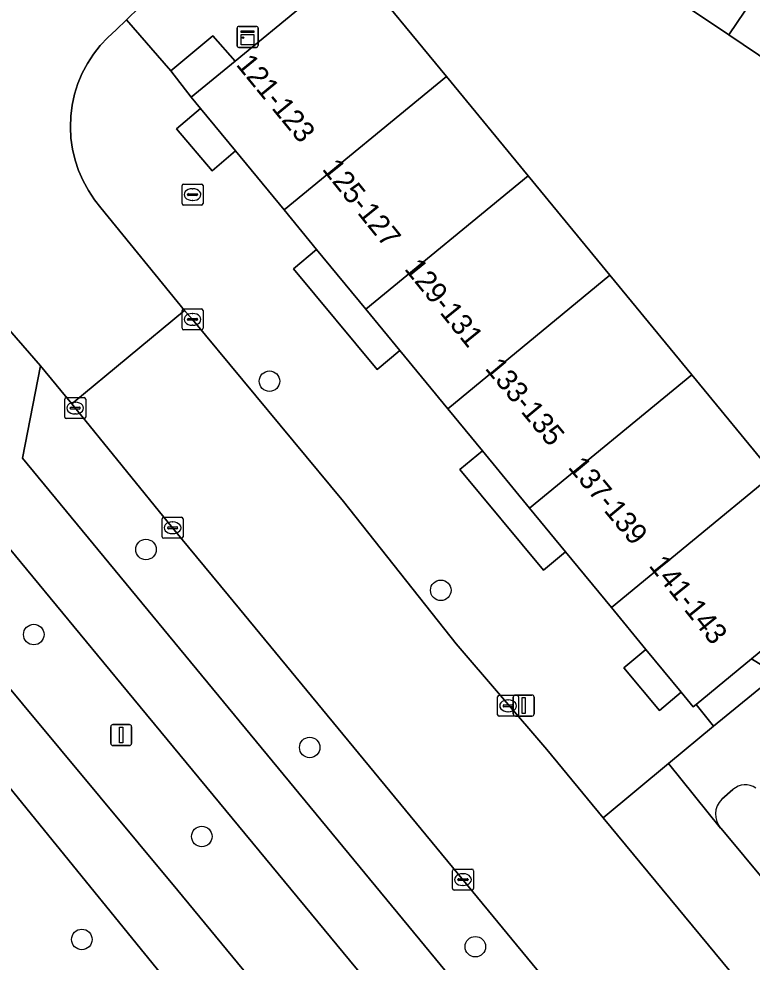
# Model space of a CAD drawing. Extents: x 159279 to 160377, y 384531 to 385888.
# Drawn here: x 159611.52 to 159646.49, y 384936.18 to 384981.15 of the extents above; entities that cross this region are included whole.
import ezdxf

# ---------------------------------------------------------------- set-up
doc = ezdxf.new("R2010")
doc.units = 0
for name, color, linetype in [('IMGEO_Berm_groen', 7, 'Continuous'), ('IMGEO_Boom', 7, 'Continuous'), ('IMGEO_Brandkraan', 7, 'Continuous'), ('IMGEO_Erf', 7, 'Continuous'), ('IMGEO_Fietspad_open', 7, 'Continuous'), ('IMGEO_Groenvoorziening', 7, 'Continuous'), ('IMGEO_Kast', 7, 'Continuous'), ('IMGEO_Kolk', 7, 'Continuous'), ('IMGEO_Lichtmast', 7, 'Continuous'), ('IMGEO_Pand', 7, 'Continuous'), ('IMGEO_Pand_nummerreeks', 7, 'Continuous'), ('IMGEO_Rijbaan_lokaal_open', 7, 'Continuous'), ('IMGEO_Voetpad_halfverhard', 7, 'Continuous'), ('IMGEO_Voetpad_open', 7, 'Continuous')]:
    doc.layers.add(name, color=color, linetype=linetype)

msp = doc.modelspace()

# ---------------------------------------------------------------- linework, layer by layer
at = {"layer": 'IMGEO_Berm_groen'}
for points in [[(159644.994, 384925.184), (159640.15, 384931.055), (159637.855, 384933.836), (159632.942, 384939.791), (159621.521, 384953.652), (159618.858, 384956.883), (159614.051, 384962.787), (159612.55, 384964.603), (159611.693, 384960.205), (159637.6, 384928.803), (159664.904, 384895.82), (159666.72, 384893.575), (159667.536, 384892.609), (159672.097, 384887.337), (159677.11, 384882.494), (159678.409, 384881.386), (159681.234, 384884.662), (159679.004, 384886.957), (159668.558, 384897.795)], [(159633.273, 384929.038), (159616.704, 384949.08), (159611.069, 384955.91), (159609.789, 384950.769), (159619.101, 384939.596), (159642.409, 384911.351), (159643.599, 384910.093), (159663.539, 384885.894)]]:
    msp.add_lwpolyline(points, dxfattribs=at)
at = {"layer": 'IMGEO_Boom'}
for centre in [(159623.475, 384963.871), (159617.585, 384955.848), (159631.643, 384953.903), (159612.235, 384951.792), (159625.394, 384946.411), (159620.248, 384942.166), (159614.527, 384937.258), (159633.291, 384936.911)]:
    msp.add_circle(centre, 0.489, dxfattribs=at)
at = {"layer": 'IMGEO_Brandkraan'}
for p, q in [((159619.305, 384972.343), (159619.305, 384973.195)), ((159619.38, 384973.269), (159620.232, 384973.269)), ((159619.793, 384973.049), (159619.818, 384973.049)), ((159620.306, 384973.195), (159620.306, 384972.343)), ((159619.564, 384972.763), (159619.564, 384972.775)), ((159620.002, 384972.726), (159619.604, 384972.726)), ((159619.607, 384972.812), (159620.005, 384972.812)), ((159619.816, 384972.489), (159619.791, 384972.489)), ((159620.048, 384972.775), (159620.048, 384972.763)), ((159620.232, 384972.269), (159619.38, 384972.269))]:
    msp.add_line(p, q, dxfattribs=at)
for points in [[(159619.305, 384972.343), (159619.305, 384973.195)], [(159619.38, 384973.269), (159620.232, 384973.269)], [(159620.306, 384973.195), (159620.306, 384972.343)], [(159620.232, 384972.269), (159619.38, 384972.269)]]:
    msp.add_lwpolyline(points, dxfattribs=at)
for centre, radius, start, end in [((159619.382, 384973.193), 0.0765, 91.552, 178.448), ((159619.382, 384973.193), 0.0765, 91.552, 178.448), ((159620.23, 384973.193), 0.0765, 1.552, 88.448), ((159620.23, 384973.193), 0.0765, 1.552, 88.448), ((159619.604, 384972.772), 0.0403, 85.8775, 175.7526), ((159619.601, 384972.762), 0.0366, 178.938, 274.7102), ((159620.005, 384972.769), 0.043, 264.8664, 352.4533), ((159620.009, 384972.774), 0.0386, 1.7309, 96.639), ((159619.382, 384972.345), 0.0765, 181.552, 268.448), ((159619.382, 384972.345), 0.0765, 181.552, 268.448), ((159620.23, 384972.345), 0.0765, 271.552, 358.448), ((159620.23, 384972.345), 0.0765, 271.552, 358.448)]:
    msp.add_arc(centre, radius, start, end, dxfattribs=at)
for centre, major_axis, ratio, start_param, end_param in [((159619.792, 384972.769), (-0.387, 0.002), 0.722429, 4.712389, 7.853982), ((159619.817, 384972.769), (-0.39, 0.002), 0.717154, 1.570796, 4.712389)]:
    msp.add_ellipse(centre, major_axis=major_axis, ratio=ratio, start_param=start_param, end_param=end_param, dxfattribs=at)
at = {"layer": 'IMGEO_Erf'}
msp.add_lwpolyline([(159660.128, 384970.454), (159658.021, 384971.872), (159655.913, 384973.29), (159653.806, 384974.708), (159651.699, 384976.126), (159649.591, 384977.544), (159647.484, 384978.963), (159645.377, 384980.381), (159643.269, 384981.799), (159641.162, 384983.217), (159639.055, 384984.635), (159640.555, 384986.863), (159642.662, 384985.445), (159644.769, 384984.027), (159646.877, 384982.609), (159648.984, 384981.191), (159651.091, 384979.773), (159653.199, 384978.355), (159655.306, 384976.937), (159657.413, 384975.519), (159659.521, 384974.101), (159661.628, 384972.683), (159663.761, 384971.248), (159662.262, 384969.019)], close=True, dxfattribs=at)
msp.add_lwpolyline([(159625.123, 384981.838), (159627.485, 384983.785), (159631.916, 384978.405), (159635.813, 384973.663), (159639.71, 384968.922), (159643.607, 384964.181), (159647.503, 384959.44)], dxfattribs=at)
at = {"layer": 'IMGEO_Fietspad_open'}
msp.add_lwpolyline([(159637.6, 384928.803), (159611.693, 384960.205), (159612.55, 384964.603), (159610.018, 384967.509), (159609.905, 384967.64), (159609.049, 384963.374), (159597.738, 384977.083), (159595.245, 384975.018), (159595.683, 384974.49), (159603.858, 384964.651), (159608.885, 384958.557), (159609.221, 384958.15), (159611.069, 384955.91), (159616.704, 384949.08), (159633.273, 384929.038), (159641.684, 384918.846), (159646.291, 384913.294), (159653.523, 384904.47)], dxfattribs=at)
at = {"layer": 'IMGEO_Groenvoorziening'}
for points in [[(159663.23, 384881.856), (159641.152, 384908.338), (159619.729, 384933.865), (159611.086, 384944.483)], [(159645.567, 384944.403), (159645.039, 384943.946)], [(159645.006, 384942.551), (159650.423, 384936.055), (159653.648, 384934.296), (159660.389, 384926.303), (159662.126, 384927.047)]]:
    msp.add_lwpolyline(points, dxfattribs=at)
for centre, radius, start, end in [((159646.165, 384943.725), 0.904, 55.8605, 131.389), ((159645.749, 384943.231), 1.008, 134.8302, 222.4595)]:
    msp.add_arc(centre, radius, start, end, dxfattribs=at)
at = {"layer": 'IMGEO_Kast'}
for p, q in [((159621.931, 384979.862), (159621.931, 384980.703)), ((159621.931, 384980.703), (159621.931, 384979.862)), ((159622.006, 384980.787), (159622.847, 384980.787)), ((159622.847, 384980.787), (159622.006, 384980.787)), ((159622.931, 384980.712), (159622.931, 384979.871)), ((159622.931, 384979.871), (159622.931, 384980.712)), ((159622.856, 384979.787), (159622.015, 384979.787)), ((159622.015, 384979.787), (159622.856, 384979.787))]:
    msp.add_line(p, q, dxfattribs=at)
for points in [[(159622.126, 384980.577), (159622.726, 384980.577), (159622.726, 384980.492), (159622.126, 384980.492), (159622.126, 384980.577)], [(159622.126, 384980.402), (159622.726, 384980.402), (159622.726, 384979.913), (159622.126, 384979.913), (159622.126, 384980.402)]]:
    msp.add_lwpolyline(points, dxfattribs=at)
msp.add_circle((159622.21, 384980.251), 0.0377, dxfattribs=at)
for centre, start, end in [((159622.009, 384980.709), 92.4484, 184.2845), ((159622.009, 384980.709), 92.4484, 184.2845), ((159622.853, 384980.709), 2.4484, 94.2845), ((159622.853, 384980.709), 2.4484, 94.2845), ((159622.009, 384979.865), 182.4484, 274.2845), ((159622.009, 384979.865), 182.4484, 274.2845), ((159622.853, 384979.865), 272.4484, 4.2845), ((159622.853, 384979.865), 272.4484, 4.2845)]:
    msp.add_arc(centre, 0.0779, start, end, dxfattribs=at)
at = {"layer": 'IMGEO_Kolk'}
for p, q in [((159619.304, 384966.393), (159619.304, 384967.245)), ((159619.379, 384967.319), (159620.231, 384967.319)), ((159619.792, 384967.099), (159619.817, 384967.099)), ((159620.305, 384967.245), (159620.305, 384966.393)), ((159619.563, 384966.813), (159619.563, 384966.825)), ((159620.001, 384966.776), (159619.603, 384966.776)), ((159619.606, 384966.862), (159620.004, 384966.862)), ((159620.047, 384966.825), (159620.047, 384966.813)), ((159620.231, 384966.319), (159619.379, 384966.319)), ((159619.815, 384966.539), (159619.79, 384966.539)), ((159613.709, 384962.163), (159613.709, 384963.015)), ((159613.784, 384963.089), (159614.636, 384963.089)), ((159614.71, 384963.015), (159614.71, 384962.163)), ((159613.968, 384962.583), (159613.968, 384962.595)), ((159614.406, 384962.546), (159614.008, 384962.546)), ((159614.011, 384962.632), (159614.409, 384962.632)), ((159614.197, 384962.869), (159614.222, 384962.869)), ((159614.452, 384962.595), (159614.452, 384962.583)), ((159614.636, 384962.089), (159613.784, 384962.089)), ((159614.22, 384962.309), (159614.195, 384962.309)), ((159618.356, 384956.457), (159618.356, 384957.309)), ((159618.431, 384957.383), (159619.283, 384957.383)), ((159618.844, 384957.163), (159618.869, 384957.163)), ((159619.357, 384957.309), (159619.357, 384956.457)), ((159618.615, 384956.877), (159618.615, 384956.889)), ((159619.053, 384956.84), (159618.655, 384956.84)), ((159618.658, 384956.926), (159619.056, 384956.926)), ((159619.099, 384956.889), (159619.099, 384956.877)), ((159619.283, 384956.383), (159618.431, 384956.383)), ((159618.867, 384956.603), (159618.842, 384956.603)), ((159634.353, 384947.97), (159634.353, 384948.822)), ((159634.428, 384948.896), (159635.28, 384948.896)), ((159634.841, 384948.676), (159634.866, 384948.676)), ((159635.354, 384948.822), (159635.354, 384947.97)), ((159634.612, 384948.39), (159634.612, 384948.402)), ((159635.05, 384948.353), (159634.652, 384948.353)), ((159634.655, 384948.439), (159635.053, 384948.439)), ((159635.096, 384948.402), (159635.096, 384948.39)), ((159635.28, 384947.896), (159634.428, 384947.896)), ((159634.864, 384948.116), (159634.839, 384948.116)), ((159632.201, 384939.684), (159632.201, 384940.536)), ((159632.276, 384940.61), (159633.128, 384940.61)), ((159633.202, 384940.536), (159633.202, 384939.684)), ((159632.46, 384940.104), (159632.46, 384940.116)), ((159632.898, 384940.067), (159632.5, 384940.067)), ((159632.503, 384940.153), (159632.901, 384940.153)), ((159632.689, 384940.39), (159632.714, 384940.39)), ((159632.944, 384940.116), (159632.944, 384940.104)), ((159633.128, 384939.61), (159632.276, 384939.61)), ((159632.712, 384939.83), (159632.687, 384939.83))]:
    msp.add_line(p, q, dxfattribs=at)
for points in [[(159619.304, 384966.393), (159619.304, 384967.245)], [(159619.379, 384967.319), (159620.231, 384967.319)], [(159620.305, 384967.245), (159620.305, 384966.393)], [(159620.231, 384966.319), (159619.379, 384966.319)], [(159613.709, 384962.163), (159613.709, 384963.015)], [(159613.784, 384963.089), (159614.636, 384963.089)], [(159614.71, 384963.015), (159614.71, 384962.163)], [(159614.636, 384962.089), (159613.784, 384962.089)], [(159618.356, 384956.457), (159618.356, 384957.309)], [(159618.431, 384957.383), (159619.283, 384957.383)], [(159619.357, 384957.309), (159619.357, 384956.457)], [(159619.283, 384956.383), (159618.431, 384956.383)], [(159634.353, 384947.97), (159634.353, 384948.822)], [(159634.428, 384948.896), (159635.28, 384948.896)], [(159635.354, 384948.822), (159635.354, 384947.97)], [(159635.28, 384947.896), (159634.428, 384947.896)], [(159632.201, 384939.684), (159632.201, 384940.536)], [(159632.276, 384940.61), (159633.128, 384940.61)], [(159633.202, 384940.536), (159633.202, 384939.684)], [(159633.128, 384939.61), (159632.276, 384939.61)]]:
    msp.add_lwpolyline(points, dxfattribs=at)
for centre, radius, start, end in [((159619.381, 384967.243), 0.0765, 91.552, 178.448), ((159619.381, 384967.243), 0.0765, 91.552, 178.448), ((159620.229, 384967.243), 0.0765, 1.552, 88.448), ((159620.229, 384967.243), 0.0765, 1.552, 88.448), ((159619.603, 384966.822), 0.0403, 85.8775, 175.7526), ((159619.6, 384966.812), 0.0366, 178.938, 274.7102), ((159620.004, 384966.819), 0.043, 264.8664, 352.4533), ((159620.008, 384966.824), 0.0386, 1.7309, 96.639), ((159619.381, 384966.395), 0.0765, 181.552, 268.448), ((159619.381, 384966.395), 0.0765, 181.552, 268.448), ((159620.229, 384966.395), 0.0765, 271.552, 358.448), ((159620.229, 384966.395), 0.0765, 271.552, 358.448), ((159613.786, 384963.013), 0.0765, 91.552, 178.448), ((159613.786, 384963.013), 0.0765, 91.552, 178.448), ((159614.634, 384963.013), 0.0765, 1.552, 88.448), ((159614.634, 384963.013), 0.0765, 1.552, 88.448), ((159614.008, 384962.592), 0.0403, 85.8775, 175.7526), ((159614.005, 384962.582), 0.0366, 178.938, 274.7102), ((159614.409, 384962.589), 0.043, 264.8664, 352.4533), ((159614.413, 384962.594), 0.0386, 1.7309, 96.639), ((159613.786, 384962.165), 0.0765, 181.552, 268.448), ((159613.786, 384962.165), 0.0765, 181.552, 268.448), ((159614.634, 384962.165), 0.0765, 271.552, 358.448), ((159614.634, 384962.165), 0.0765, 271.552, 358.448), ((159618.433, 384957.307), 0.0765, 91.552, 178.448), ((159618.433, 384957.307), 0.0765, 91.552, 178.448), ((159619.281, 384957.307), 0.0765, 1.552, 88.448), ((159619.281, 384957.307), 0.0765, 1.552, 88.448), ((159618.655, 384956.886), 0.0403, 85.8775, 175.7526), ((159618.652, 384956.876), 0.0366, 178.938, 274.7102), ((159619.056, 384956.883), 0.043, 264.8664, 352.4533), ((159619.06, 384956.888), 0.0386, 1.7309, 96.639), ((159618.433, 384956.459), 0.0765, 181.552, 268.448), ((159618.433, 384956.459), 0.0765, 181.552, 268.448), ((159619.281, 384956.459), 0.0765, 271.552, 358.448), ((159619.281, 384956.459), 0.0765, 271.552, 358.448), ((159634.43, 384948.82), 0.0765, 91.552, 178.448), ((159634.43, 384948.82), 0.0765, 91.552, 178.448), ((159635.278, 384948.82), 0.0765, 1.552, 88.448), ((159635.278, 384948.82), 0.0765, 1.552, 88.448), ((159634.652, 384948.399), 0.0403, 85.8775, 175.7526), ((159634.649, 384948.389), 0.0366, 178.938, 274.7102), ((159635.053, 384948.396), 0.043, 264.8664, 352.4533), ((159635.057, 384948.401), 0.0386, 1.7309, 96.639), ((159634.43, 384947.972), 0.0765, 181.552, 268.448), ((159634.43, 384947.972), 0.0765, 181.552, 268.448), ((159635.278, 384947.972), 0.0765, 271.552, 358.448), ((159635.278, 384947.972), 0.0765, 271.552, 358.448), ((159632.278, 384940.534), 0.0765, 91.552, 178.448), ((159632.278, 384940.534), 0.0765, 91.552, 178.448), ((159633.126, 384940.534), 0.0765, 1.552, 88.448), ((159633.126, 384940.534), 0.0765, 1.552, 88.448), ((159632.5, 384940.113), 0.0403, 85.8775, 175.7526), ((159632.497, 384940.103), 0.0366, 178.938, 274.7102), ((159632.901, 384940.11), 0.043, 264.8664, 352.4533), ((159632.905, 384940.115), 0.0386, 1.7309, 96.639), ((159632.278, 384939.686), 0.0765, 181.552, 268.448), ((159632.278, 384939.686), 0.0765, 181.552, 268.448), ((159633.126, 384939.686), 0.0765, 271.552, 358.448), ((159633.126, 384939.686), 0.0765, 271.552, 358.448)]:
    msp.add_arc(centre, radius, start, end, dxfattribs=at)
for centre, major_axis, ratio, start_param, end_param in [((159619.791, 384966.819), (-0.387, 0.002), 0.722429, 4.712389, 7.853982), ((159619.816, 384966.819), (-0.39, 0.002), 0.717154, 1.570796, 4.712389), ((159614.196, 384962.589), (-0.387, 0.002), 0.722429, 4.712389, 7.853982), ((159614.221, 384962.589), (-0.39, 0.002), 0.717154, 1.570796, 4.712389), ((159618.843, 384956.883), (-0.387, 0.002), 0.722429, 4.712389, 7.853982), ((159618.868, 384956.883), (-0.39, 0.002), 0.717154, 1.570796, 4.712389), ((159634.84, 384948.396), (-0.387, 0.002), 0.722429, 4.712389, 7.853982), ((159634.865, 384948.396), (-0.39, 0.002), 0.717154, 1.570796, 4.712389), ((159632.688, 384940.11), (-0.387, 0.002), 0.722429, 4.712389, 7.853982), ((159632.713, 384940.11), (-0.39, 0.002), 0.717154, 1.570796, 4.712389)]:
    msp.add_ellipse(centre, major_axis=major_axis, ratio=ratio, start_param=start_param, end_param=end_param, dxfattribs=at)
at = {"layer": 'IMGEO_Lichtmast'}
for p, q in [((159635.099, 384948.01), (159635.099, 384948.81)), ((159635.099, 384948.81), (159635.099, 384948.01)), ((159635.199, 384948.91), (159635.989, 384948.91)), ((159635.989, 384948.91), (159635.199, 384948.91)), ((159636.089, 384948.81), (159636.089, 384948.01)), ((159636.089, 384948.01), (159636.089, 384948.81)), ((159635.989, 384947.91), (159635.199, 384947.91)), ((159635.199, 384947.91), (159635.989, 384947.91)), ((159615.908, 384946.6), (159615.908, 384947.4)), ((159615.908, 384947.4), (159615.908, 384946.6)), ((159616.008, 384947.5), (159616.798, 384947.5)), ((159616.798, 384947.5), (159616.008, 384947.5)), ((159616.898, 384947.4), (159616.898, 384946.6)), ((159616.898, 384946.6), (159616.898, 384947.4)), ((159616.798, 384946.5), (159616.008, 384946.5)), ((159616.008, 384946.5), (159616.798, 384946.5))]:
    msp.add_line(p, q, dxfattribs=at)
for points in [[(159635.519, 384948.785), (159635.669, 384948.785), (159635.669, 384948.035), (159635.519, 384948.035), (159635.519, 384948.785)], [(159616.328, 384947.375), (159616.478, 384947.375), (159616.478, 384946.625), (159616.328, 384946.625), (159616.328, 384947.375)]]:
    msp.add_lwpolyline(points, dxfattribs=at)
for centre, start, end in [((159635.199, 384948.81), 90, 180), ((159635.199, 384948.81), 90, 180), ((159635.989, 384948.81), 0, 90), ((159635.989, 384948.81), 360, 90), ((159635.199, 384948.01), 180, 270), ((159635.199, 384948.01), 180, 270), ((159635.989, 384948.01), 270, 0), ((159635.989, 384948.01), 270, 0), ((159616.008, 384947.4), 90, 180), ((159616.008, 384947.4), 90, 180), ((159616.798, 384947.4), 0, 90), ((159616.798, 384947.4), 360, 90), ((159616.008, 384946.6), 180, 270), ((159616.008, 384946.6), 180, 270), ((159616.798, 384946.6), 270, 0), ((159616.798, 384946.6), 270, 0)]:
    msp.add_arc(centre, 0.1, start, end, dxfattribs=at)
at = {"layer": 'IMGEO_Pand'}
for points in [[(159624.169, 384972.035), (159631.916, 384978.405), (159627.485, 384983.785), (159625.123, 384981.838), (159621.833, 384979.127), (159619.744, 384977.406), (159620.188, 384976.867), (159621.85, 384974.85)], [(159646.877, 384982.609), (159644.769, 384984.027), (159643.269, 384981.799), (159645.377, 384980.381)], [(159648.984, 384981.191), (159646.877, 384982.609), (159645.377, 384980.381), (159647.484, 384978.963)], [(159628.071, 384967.298), (159635.813, 384973.663), (159631.916, 384978.405), (159624.169, 384972.035), (159625.719, 384970.153)], [(159631.973, 384962.562), (159639.71, 384968.922), (159635.813, 384973.663), (159628.071, 384967.298), (159629.688, 384965.335)], [(159635.875, 384957.825), (159643.607, 384964.181), (159639.71, 384968.922), (159631.973, 384962.562), (159633.628, 384960.553)], [(159639.777, 384953.088), (159647.503, 384959.44), (159643.607, 384964.181), (159635.875, 384957.825), (159637.596, 384955.736)], [(159641.427, 384951.086), (159643.109, 384949.044), (159643.686, 384948.344), (159643.826, 384948.459), (159646.463, 384950.632), (159649.084, 384952.791), (159651.4, 384954.699), (159647.503, 384959.44), (159639.777, 384953.088)], [(159652.211, 384950.895), (159649.084, 384952.791), (159646.463, 384950.632), (159647.662, 384949.889), (159650.631, 384948.05), (159654.45, 384945.627), (159656.129, 384948.52)]]:
    msp.add_lwpolyline(points, close=True, dxfattribs=at)
at = {"layer": 'IMGEO_Rijbaan_lokaal_open'}
for points in [[(159610.018, 384967.509), (159612.55, 384964.603), (159614.051, 384962.787), (159619.429, 384967.245), (159615.439, 384972.141), (159615.132, 384972.524), (159614.838, 384972.964), (159614.584, 384973.429), (159614.373, 384973.914), (159614.206, 384974.416), (159614.085, 384974.931), (159614.01, 384975.455), (159613.982, 384975.984), (159614.001, 384976.513), (159614.068, 384977.038), (159614.181, 384977.555), (159614.34, 384978.06), (159614.544, 384978.549), (159614.79, 384979.017), (159615.078, 384979.462), (159615.403, 384979.879), (159615.765, 384980.265), (159616.16, 384980.618), (159616.655, 384981.099), (159617.277, 384981.702)], [(159648.282, 384932.298), (159639.384, 384943.06), (159636.696, 384946.32), (159632.384, 384951.356), (159627.012, 384958.142), (159619.804, 384966.819), (159619.429, 384967.245), (159614.051, 384962.787), (159618.858, 384956.883), (159621.521, 384953.652), (159632.942, 384939.791), (159637.855, 384933.836), (159640.15, 384931.055), (159644.994, 384925.184), (159659.927, 384907.465)]]:
    msp.add_lwpolyline(points, dxfattribs=at)
at = {"layer": 'IMGEO_Voetpad_halfverhard'}
msp.add_lwpolyline([(159663.539, 384885.894), (159643.599, 384910.093), (159642.409, 384911.351), (159619.101, 384939.596), (159609.789, 384950.769), (159607.67, 384948.458), (159610.2, 384945.691), (159611.086, 384944.483), (159619.729, 384933.865), (159641.152, 384908.338), (159663.23, 384881.856)], dxfattribs=at)
at = {"layer": 'IMGEO_Voetpad_open'}
for points in [[(159628.785, 384995.174), (159627.072, 384995.028), (159626.924, 384994.948), (159626.783, 384994.856), (159626.651, 384994.751), (159626.529, 384994.635), (159626.418, 384994.508), (159626.328, 384994.386), (159624.758, 384991.915), (159622.562, 384988.574), (159622.355, 384988.248), (159620.032, 384984.953), (159617.424, 384981.879), (159617.277, 384981.702), (159616.655, 384981.099), (159618.777, 384978.67), (159620.777, 384980.34), (159621.833, 384979.127), (159625.123, 384981.838)], [(159653.389, 384943.716), (159654.078, 384944.948), (159654.45, 384945.627), (159650.631, 384948.05), (159647.662, 384949.889), (159644.648, 384947.431), (159642.498, 384945.646), (159644.984, 384942.563), (159645.006, 384942.551)], [(159653.648, 384934.296), (159650.423, 384936.055), (159645.006, 384942.551), (159644.984, 384942.563), (159642.498, 384945.646), (159639.384, 384943.06), (159648.282, 384932.298)], [(159645.039, 384943.946), (159645.567, 384944.403)]]:
    msp.add_lwpolyline(points, dxfattribs=at)
for points in [[(159629.688, 384965.335), (159628.605, 384964.435), (159624.616, 384969.236), (159625.719, 384970.153), (159624.169, 384972.035), (159621.85, 384974.85), (159620.741, 384973.905), (159619.046, 384975.895), (159620.188, 384976.867), (159619.744, 384977.406), (159618.777, 384978.67), (159616.655, 384981.099), (159616.16, 384980.618), (159615.765, 384980.265), (159615.403, 384979.879), (159615.078, 384979.462), (159614.79, 384979.017), (159614.544, 384978.549), (159614.34, 384978.06), (159614.181, 384977.555), (159614.068, 384977.038), (159614.001, 384976.513), (159613.982, 384975.984), (159614.01, 384975.455), (159614.085, 384974.931), (159614.206, 384974.416), (159614.373, 384973.914), (159614.584, 384973.429), (159614.838, 384972.964), (159615.132, 384972.524), (159615.439, 384972.141), (159619.429, 384967.245), (159619.804, 384966.819), (159627.012, 384958.142), (159632.384, 384951.356), (159636.696, 384946.32), (159639.384, 384943.06), (159642.498, 384945.646), (159644.648, 384947.431), (159643.826, 384948.459), (159643.686, 384948.344), (159643.109, 384949.044), (159642.069, 384948.173), (159640.37, 384950.201), (159641.427, 384951.086), (159639.777, 384953.088), (159637.596, 384955.736), (159636.535, 384954.858), (159632.558, 384959.668), (159633.628, 384960.553), (159631.973, 384962.562)], [(159620.777, 384980.34), (159618.777, 384978.67), (159619.744, 384977.406), (159621.833, 384979.127)], [(159619.046, 384975.895), (159620.741, 384973.905), (159621.85, 384974.85), (159620.188, 384976.867)], [(159625.719, 384970.153), (159624.616, 384969.236), (159628.605, 384964.435), (159629.688, 384965.335), (159628.071, 384967.298)], [(159633.628, 384960.553), (159632.558, 384959.668), (159636.535, 384954.858), (159637.596, 384955.736), (159635.875, 384957.825)], [(159640.37, 384950.201), (159642.069, 384948.173), (159643.109, 384949.044), (159641.427, 384951.086)], [(159644.648, 384947.431), (159647.662, 384949.889), (159646.463, 384950.632), (159643.826, 384948.459)]]:
    msp.add_lwpolyline(points, close=True, dxfattribs=at)
for centre, radius, start, end in [((159646.165, 384943.725), 0.904, 55.8605, 131.389), ((159645.749, 384943.231), 1.008, 134.8302, 222.4595)]:
    msp.add_arc(centre, radius, start, end, dxfattribs=at)

# ---------------------------------------------------------------- texts
at = {"layer": 'IMGEO_Pand_nummerreeks'}
for s, rotation, p in [('121-123', 309.3391, (159621.847, 384978.956)), ('125-127', 308.8521, (159625.954, 384973.975)), ('129-131', 309.0526, (159629.876, 384969.215)), ('133-135', 309.7516, (159633.717, 384964.473)), ('137-139', 309.7516, (159637.676, 384959.758)), ('141-143', 308.726, (159641.534, 384955.068))]:
    msp.add_text(s, height=1, rotation=rotation, dxfattribs=at).set_placement(p)

doc.saveas('drawing.dxf')
